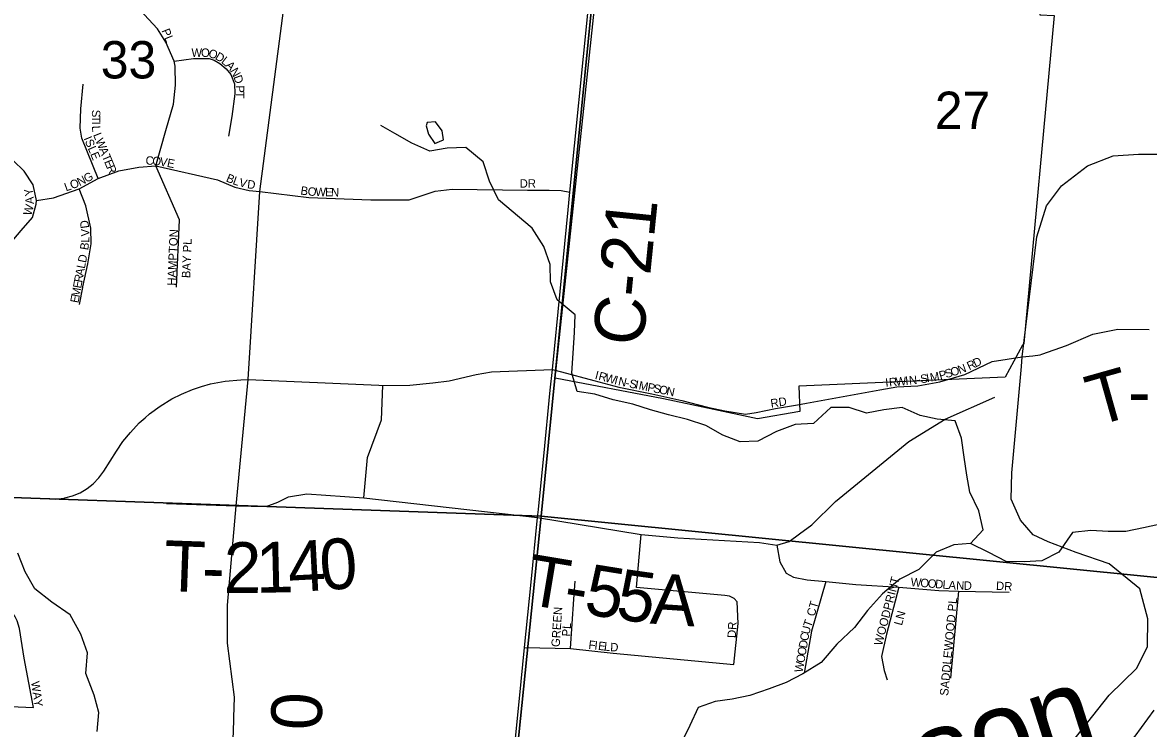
# Model space of a CAD drawing. Extents: x 1310247 to 1664935, y 284496 to 704931.
# Drawn here: x 1452162 to 1458833, y 480206 to 484384 of the extents above; entities that cross this region are included whole.
import ezdxf

# ---------------------------------------------------------------- set-up
doc = ezdxf.new("R2010")
doc.units = 0
for name, color, linetype in [('GM_P_State_Location', 7, 'Continuous'), ('GM_X_Corporation_Text', 7, 'Continuous'), ('GM_X_County', 7, 'Continuous'), ('GM_X_County_Road_Text', 7, 'Continuous'), ('GM_X_County_Subdivision_Text', 7, 'Continuous'), ('GM_X_Major_Lake_Text', 7, 'Continuous'), ('GM_X_Minor_Lake_Text', 7, 'Continuous'), ('GM_X_Minor_River', 7, 'Continuous'), ('GM_X_Minor_River_Text', 7, 'Continuous'), ('GM_X_Rail_Line', 7, 'Continuous'), ('GM_X_State_Location', 7, 'Continuous'), ('GM_X_State_Shield', 7, 'Continuous'), ('GM_X_Township_Road', 7, 'Continuous'), ('GM_X_Township_Subdivision', 7, 'Continuous'), ('GM_X_US_Location', 7, 'Continuous')]:
    doc.layers.add(name, color=color, linetype=linetype)

msp = doc.modelspace()

# ---------------------------------------------------------------- linework, layer by layer
at = {"layer": 'GM_X_Corporation_Text'}
for points in [[(1457240.8, 482210.7), (1457342.4, 482229.3), (1457466.3, 482234.8), (1457595.8, 482258.9), (1457743.8, 482301.5), (1457906.6, 482379.2), (1458084.2, 482405.1), (1458147.6, 482412.7)], [(1455354.4, 482317.2), (1455547.2, 482266.6), (1455694.9, 482227), (1455889.9, 482187.4), (1456069.2, 482147.9), (1456219.5, 482108.3), (1456322.3, 482087.2), (1456446.2, 482066.1), (1456509.5, 482076.7), (1456622.6, 482101.1), (1456753.5, 482121.5), (1456807.2, 482131.3)]]:
    msp.add_lwpolyline(points, dxfattribs=at)
at = {"layer": 'GM_X_County'}
for points in [[(1455772.4, 486880.5), (1455235.5, 481463.8), (1449969.8, 481647.7), (1450514.7, 486966.2)], [(1455772.4, 486880.5), (1461130.9, 486442.7), (1460590.1, 480930.2), (1455235.5, 481463.8)], [(1455235.5, 481463.8), (1454675.8, 475995.7), (1449464.2, 476312.3), (1449969.8, 481647.7)], [(1455235.5, 481463.8), (1460590.1, 480930.2), (1460069.6, 475529), (1454675.8, 475995.7)]]:
    msp.add_lwpolyline(points, close=True, dxfattribs=at)
at = {"layer": 'GM_X_County_Road_Text'}
for points in [[(1453375.8, 480739.7), (1453375.8, 480936.7), (1453428.9, 481523.2), (1453498.8, 482271.3), (1453567.4, 483383.7), (1453751.2, 484788.5), (1453817.5, 485658.8)], [(1455395.2, 483276.2), (1455405.6, 483381.2), (1455512.9, 484458.4)], [(1458271.1, 479989.5), (1458600.4, 480404), (1458763.2, 480563.1), (1458826.1, 480690.8), (1458829.7, 480855.5), (1458781.6, 481033.1), (1458600.4, 481181.1), (1458404.3, 481247.7), (1458237.8, 481310.7), (1458149, 481353.2), (1458075, 481438.3), (1458019.5, 481564.1), (1458023.2, 481719.5), (1458080.5, 482349), (1458084.2, 482405.1), (1458171.2, 483115.6), (1458228.5, 483298.8), (1458317.3, 483417.2), (1458470.6, 483537.3), (1458624.4, 483594.8), (1458772.6, 483604.9), (1459218.6, 483605.9)], [(1455347, 482792.6), (1455395.2, 483276.2)], [(1455282.7, 482147.8), (1455288.8, 482208.2), (1455301.1, 482331.2), (1455347, 482792.6)], [(1455255.9, 481879.1), (1455282.7, 482147.8)], [(1455218.3, 481502.9), (1455255.9, 481879.1)], [(1455175.3, 481073.1), (1455213.5, 481454.4), (1455218.3, 481502.9)], [(1454713.6, 476457.2), (1454761.4, 476935.6), (1454804.8, 477382.3), (1454822.6, 477547.1), (1454848.9, 477809.4), (1454853, 477851.8), (1454885.7, 478192.2), (1454911.9, 478438.9), (1454938.1, 478701.1), (1454941.6, 478737.5), (1454977.6, 479107.4), (1455006.3, 479383.1), (1455043, 479750.3), (1455049.2, 479812.4), (1455116.4, 480484.6), (1455136.6, 480686.4), (1455175.3, 481073.1)], [(1453414.5, 480270.9), (1453417.9, 480392.2), (1453375.8, 480710.5), (1453375.8, 480739.7)], [(1453375.4, 479748.5), (1453411.9, 480178), (1453414.5, 480270.9)]]:
    msp.add_lwpolyline(points, dxfattribs=at)
at = {"layer": 'GM_X_County_Subdivision_Text'}
for points in [[(1458201.8, 482421.7), (1458346.9, 482473.5), (1458502.3, 482540.1), (1458650.3, 482569.8), (1458837.4, 482567.3)], [(1458147.6, 482412.7), (1458191.5, 482418), (1458201.8, 482421.7)], [(1454274, 482238), (1454296.1, 482237.1), (1454456.7, 482238.1), (1454592.7, 482251.7), (1454690.5, 482264.3), (1454849.8, 482302.2), (1454941.3, 482317.9), (1455301.1, 482331.2)], [(1455301.1, 482331.2), (1455301.1, 482331.2), (1455354.4, 482317.2)], [(1452889.5, 482045.5), (1452915.5, 482068.5), (1452978.1, 482113.9), (1453047.9, 482156.9), (1453103.9, 482185.1), (1453169.4, 482212.9), (1453223.4, 482231), (1453276.5, 482245.8), (1453362.1, 482261.6), (1453455.8, 482269.8), (1453498.8, 482271.3)], [(1453498.8, 482271.3), (1454274, 482238)], [(1454185, 481571.9), (1454206.2, 481810), (1454289.8, 482032.4), (1454296.1, 482237.1)], [(1456807.2, 482131.3), (1457240.8, 482210.7)], [(1456766.2, 481357.7), (1456839.2, 481410.7), (1456978.4, 481549.9), (1457412.7, 481904.6), (1457627.3, 482037.8), (1457922.8, 482167.1)], [(1452412.6, 481570.8), (1452457.9, 481582.7), (1452504.8, 481601.8), (1452545.9, 481626.7), (1452581.8, 481654.9), (1452614.8, 481688.8), (1452643.9, 481729), (1452719.9, 481848.5), (1452756.8, 481904), (1452802.2, 481959), (1452854.3, 482014.4), (1452889.5, 482045.5)], [(1453428.9, 481523.2), (1453605.9, 481520.7), (1453675.2, 481545.5), (1453738.4, 481577.4), (1453846.5, 481594.2), (1454185, 481571.9), (1455213.5, 481454.4)], [(1451882.1, 481582.8), (1451891.6, 481582.4), (1452287.3, 481566.9), (1452355.1, 481564.3), (1452408.7, 481569.8), (1452412.6, 481570.8)], [(1453015, 481537), (1453428.9, 481523.2)], [(1455213.5, 481454.4), (1455827.9, 481354.4), (1456044, 481333.7), (1456528.3, 481307), (1456631.9, 481292.2), (1456704.4, 481312.9), (1456766.2, 481357.7)]]:
    msp.add_lwpolyline(points, dxfattribs=at)
at = {"layer": 'GM_X_Major_Lake_Text'}
msp.add_lwpolyline([(1458591.9, 489632.4), (1458545.1, 486934), (1458284.7, 486929.5), (1458188.3, 484430.7), (1458274.2, 484426.5), (1458093.9, 482484.6), (1458086.6, 482474.1), (1457984.5, 482286.4), (1456761.6, 482232.6), (1456766.4, 482083), (1456516.1, 482039), (1456258.5, 482093.4), (1455960.3, 482157.2), (1455317.1, 482279.9), (1455774.7, 486569.4), (1455792.3, 486820.8), (1455762.4, 486822.9), (1455732.4, 486822.4), (1455736.8, 486886.2), (1455716.9, 486888), (1455687.7, 486857.7), (1455526.7, 486817.6), (1452611.3, 486766.7), (1452779, 489168.6)], dxfattribs=at)
at = {"layer": 'GM_X_Minor_River'}
for points in [[(1454631.9, 483680.8), (1454655.4, 483691.2), (1454649.4, 483743.3), (1454609.3, 483797.4), (1454559.7, 483791.9)], [(1454559.7, 483791.9), (1454553.1, 483773.3), (1454567.2, 483723.2), (1454605.3, 483669.1), (1454631.9, 483680.8)]]:
    msp.add_lwpolyline(points, dxfattribs=at)
at = {"layer": 'GM_X_Minor_River_Text'}
for points in [[(1457779.1, 481300.7), (1457853.3, 481382.9), (1457827.2, 481495.2), (1457775, 481605.4), (1457757, 481705.7), (1457740.9, 481811.9), (1457724.8, 481924.2), (1457686.7, 482026.4), (1457580.3, 482036.4), (1457480, 482058.5), (1457373.7, 482106.6), (1457265.3, 482092.6), (1457163, 482072.5), (1457058.7, 482106.6), (1456950.3, 482106.6), (1456848, 482010.4), (1456739.7, 482006.4), (1456629.3, 481964.3), (1456519, 481906.1), (1456414.6, 481902.1), (1456310.3, 481942.2), (1456210, 482000.4), (1456101.6, 482034.4), (1455989.3, 482062.5), (1455882.9, 482092.6), (1455778.6, 482126.6), (1455662.2, 482150.7), (1455551.9, 482184.8), (1455447.5, 482200.8), (1455417.4, 482309.1), (1455425.4, 482427.4), (1455431.4, 482549.6), (1455435.4, 482653.9), (1455329.1, 482744.1), (1455290.9, 482850.3), (1455288.9, 482952.6), (1455250.8, 483058.8), (1455182.5, 483167.1), (1454981.9, 483335.5), (1454929.7, 483445.7), (1454891.5, 483560), (1454789.2, 483644.2), (1454678.8, 483640.2), (1454574.5, 483624.1), (1454468.2, 483670.3), (1454367.8, 483728.4), (1454285.6, 483774.5)], [(1458920.7, 481419), (1458802.4, 481392.9), (1458698, 481372.9), (1458593.7, 481372.9), (1458491.4, 481378.9), (1458383, 481366.8), (1458300.8, 481250.6), (1458200.5, 481198.5), (1458096.1, 481192.5), (1457989.8, 481194.5), (1457887.5, 481248.6), (1457779.1, 481300.7), (1457678.8, 481292.7), (1457574.4, 481250.6), (1457472.1, 481146.3), (1457359.8, 481090.2), (1457257.5, 481004), (1457167.2, 480903.8), (1457091, 480803.5), (1456986.7, 480705.3), (1456894.4, 480597), (1456786, 480528.9), (1456685.7, 480478.8), (1456585.4, 480440.7), (1456471.1, 480400.6), (1456366.7, 480380.5), (1456266.4, 480366.5), (1456164.1, 480330.4), (1456115.9, 480224.2), (1456045.6, 480081.8)], [(1452604.8, 480188.1), (1452614.8, 480300.3), (1452586.7, 480402.6), (1452536.5, 480530.9), (1452546.5, 480653.2), (1452508.4, 480765.4), (1452444.2, 480879.7), (1452335.8, 480953.9), (1452235.5, 481032.1), (1452177.3, 481134.3), (1452135.1, 481244.6)]]:
    msp.add_lwpolyline(points, dxfattribs=at)
at = {"layer": 'GM_X_State_Location'}
for points in [[(1452952.9, 483535.8), (1453011, 483745.3), (1453057, 483900.8), (1453069.1, 484014.3), (1453066.4, 484126.5), (1453061, 484156.2), (1453012.3, 484268.4), (1452962.3, 484348.1), (1452856.9, 484459), (1452767.7, 484514.4), (1452685.3, 484552.2), (1452556.9, 484572.5), (1452415, 484559)], [(1453061, 484156.2), (1453174.6, 484172.4), (1453228.6, 484172.4), (1453267.8, 484171.1), (1453297.6, 484161.6), (1453331.3, 484142.7), (1453369.2, 484110.3), (1453396.2, 484076.5), (1453417.8, 484022.4), (1453419.2, 483962.9), (1453403, 483827.8), (1453382.7, 483711.5)], [(1452609.6, 483461.5), (1452513.1, 483700.9), (1452503.1, 483758.8), (1452508.1, 483874.6), (1452521.3, 484020.2)], [(1452092.9, 482344.4), (1452018.5, 482397.3), (1451978.7, 482450.2), (1451953.9, 482506.5), (1451942.3, 482551.2), (1451937.4, 482648.8), (1451952.3, 482784.4), (1451995.3, 482915.1), (1452079.6, 483065.6), (1452154.1, 483153.3), (1452221.9, 483231.1), (1452243.4, 483308.8), (1452244.7, 483331.7), (1452225.2, 483423), (1452172.3, 483505.7), (1452107.8, 483568.5)], [(1452244.7, 483331.7), (1452346, 483346.6), (1452497.7, 483401.2), (1452609.6, 483461.5), (1452732.6, 483506.1), (1452851.9, 483528.7), (1452952.9, 483535.8), (1453316.8, 483452.7), (1453420.6, 483410.9), (1453504.2, 483390.7), (1453567.4, 483383.7)], [(1453074.7, 482817.4), (1453093, 483215.9), (1452952.9, 483535.8)], [(1452500.1, 482715.4), (1452520.4, 482815.4), (1452520.4, 482819.5), (1452548.8, 482956), (1452569, 483075), (1452567.7, 483166.8), (1452538, 483299.3), (1452497.7, 483401.2)], [(1453567.4, 483383.7), (1453858.4, 483349.2), (1454226.8, 483335.5), (1454452, 483335.5), (1454606, 483386.3), (1454706.9, 483398.2), (1455153.6, 483391.8), (1455281.4, 483392.8), (1455352.5, 483390.8), (1455405.6, 483381.2)], [(1451678, 480354), (1452227.4, 480330.3), (1452172.4, 480622.9), (1452160.9, 480697.9), (1452144.5, 480797.8), (1452131.4, 480843.5), (1452116.8, 480870.9), (1452096.1, 480899.6), (1452077.7, 480921.6), (1452058.1, 480945.7), (1452042.7, 480974.3), (1452018.8, 481018.9), (1451978.4, 481105.4), (1451935.1, 481208.6), (1451880.5, 481340.4), (1451891.6, 481582.4)], [(1455136.6, 480686.4), (1455408.8, 480679.2), (1455660.5, 480652.5), (1456377, 480584.1), (1456402.7, 480828), (1456396.2, 480956.4), (1456377.6, 480975), (1456363.1, 480984.2), (1456349.9, 480989.5), (1456322.4, 480993.3), (1455800.5, 481040.8), (1455827.9, 481354.4)], [(1456631.9, 481292.2), (1456648.2, 481193), (1456686.7, 481126.4), (1456729, 481101.9), (1456811.1, 481086.4), (1456920.6, 481076), (1457099.8, 481058.3), (1457353, 481043.5), (1457591.4, 481022.7), (1457706.9, 481018.3), (1458007.5, 481013.8)], [(1455408.8, 480679.2), (1455428.1, 480972.4), (1455435.4, 481077.5)], [(1456920.6, 481076), (1456836.2, 480782.8), (1456793.3, 480534.1)], [(1457353, 481043.5), (1457280.5, 480765.1), (1457250.8, 480633.3), (1457267.1, 480548.9), (1457284.9, 480494.1)], [(1457706.9, 481018.3), (1457659.5, 480504.5)]]:
    msp.add_lwpolyline(points, dxfattribs=at)
at = {"layer": 'GM_X_State_Shield'}
msp.add_lwpolyline([(1456800.8, 478265.5), (1456819.9, 478282.7), (1457013.8, 478449.2), (1457150.7, 478574.8), (1457308.1, 478724), (1457514.5, 478912.4), (1457729, 479106.6), (1457937.4, 479298.9), (1458092.8, 479442.1), (1458233.9, 479575.6), (1458381.4, 479729.1), (1458496.4, 479863.1), (1458625.8, 480013), (1458753.1, 480160.8), (1458866.5, 480315)], dxfattribs=at)

# ---------------------------------------------------------------- texts
at = {"layer": 'GM_P_State_Location'}
for s, rotation, p in [('PL', 291.69565, (1452985.2, 484336.9)), ('W', 359.51246, (1453162.6, 484181.6)), ('O', 359.51909, (1453219.8, 484181.1)), ('O', 343.78439, (1453260.2, 484181.3)), ('D', 329.00251, (1453299.3, 484170.4)), ('L', 321.73692, (1453335.6, 484148.6)), ('A', 313.34577, (1453361.9, 484128.1)), ('N', 299.72321, (1453390.2, 484098.7)), ('D', 289.91403, (1453411.1, 484062.5)), ('P', 271.55776, (1453426.1, 484012.1)), ('T', 268.03258, (1453427.1, 483977.7)), ('S', 269.86338, (1452573.7, 483868.2)), ('T', 269.88232, (1452573.6, 483833)), ('I', 269.86888, (1452573.5, 483797.8)), ('L', 273.55504, (1452573.6, 483772.3)), ('L', 291.81095, (1452579.6, 483720.3)), ('ISLE', 292.9343, (1452523.5, 483698.7)), ('W', 292.54217, (1452592.9, 483687)), ('A', 292.55182, (1452614.8, 483634.1)), ('T', 292.55528, (1452631.7, 483593.5)), ('E', 292.55528, (1452645.2, 483561)), ('R', 292.56107, (1452658.7, 483528.4)), ('C', 358.11501, (1452890.7, 483543.6)), ('O', 354.34503, (1452929.4, 483542.4)), ('V', 350.57506, (1452972.4, 483538.2)), ('E', 348.69007, (1453015.3, 483531)), ('N', 26.78168, (1452500.9, 483414.9)), ('G', 27.64337, (1452540.9, 483435.1)), ('B', 337.02145, (1453364.4, 483446)), ('L', 340.57365, (1453404, 483429.4)), ('V', 345.56897, (1453441.7, 483416.3)), ('Y', 101.45654, (1452227.9, 483363.2)), ('L', 19.6189, (1452420.4, 483384.7)), ('O', 20.97915, (1452454.7, 483397)), ('D', 353.04598, (1453491.2, 483404)), ('B', 351.19659, (1453806.8, 483367.5)), ('O', 356.24318, (1453850.6, 483360.9)), ('W', 358.58763, (1453896.8, 483357.9)), ('E', 358.59946, (1453954, 483356.5)), ('N', 358.59662, (1453989.2, 483355.6)), ('DR', 0.00001, (1455107.5, 483407.2)), ('A', 92.13508, (1452230.6, 483310.4)), ('W', 74.58118, (1452213.4, 483238.7)), ('D', 98.59042, (1452557.6, 483169.9)), ('V', 91.16462, (1452559.1, 483119)), ('HAMPTON', 87.51181, (1453069.7, 482826.2)), ('B', 80.63348, (1452550.8, 483034.9)), ('L', 88.04732, (1452557.9, 483080.9)), ('BAY PL', 87.66396, (1453155.6, 482871.1)), ('D', 77.44274, (1452537.7, 482959.3)), ('L', 79.03295, (1452531.1, 482925.1)), ('R', 79.49967, (1452515.9, 482843.1)), ('A', 79.4918, (1452523.1, 482882)), ('M', 79.48663, (1452499.8, 482756.5)), ('E', 79.51094, (1452509.5, 482808.4)), ('E', 79.50453, (1452493.4, 482721.9)), ('WOODPRINT', 75.46732, (1457254.2, 480693.7)), ('W', 355.62451, (1457422.6, 481048.8)), ('O', 355.61232, (1457479.6, 481044.4)), ('O', 355.62476, (1457523.5, 481041.1)), ('D', 355.61232, (1457567.3, 481037.7)), ('L', 355.62435, (1457611.2, 481034.3)), ('A', 355.61232, (1457646.3, 481031.7)), ('N', 358.32641, (1457692.8, 481028.2)), ('D', 359.92533, (1457738.3, 481026.9)), ('DR', 356.81008, (1457928.4, 481026.8)), ('CT', 73.60558, (1456854, 480866.1)), ('SADDLEWOOD PL', 84.67348, (1457645.7, 480397.9)), ('GREEN', 86.27045, (1455344.5, 480687.2)), ('LN', 74.48215, (1457371.6, 480812.4)), ('PL', 86.42535, (1455407.4, 480749.5)), ('DR', 86.98841, (1456387.9, 480740.7)), ('U', 76.34016, (1456822.9, 480759.6)), ('T', 70.8221, (1456833, 480801.1)), ('F', 353.48485, (1455513.3, 480678.5)), ('D', 80.01241, (1456808.6, 480678.1)), ('C', 79.99061, (1456816.2, 480721.4)), ('I', 353.47151, (1455548.3, 480674.5)), ('E', 353.49922, (1455570.2, 480672)), ('L', 353.48485, (1455605.2, 480668)), ('D', 356.41869, (1455642.9, 480663.8)), ('O', 79.98441, (1456800.9, 480634.7)), ('W', 79.99591, (1456783.4, 480535)), ('O', 80.01241, (1456793.3, 480591.4)), ('WAY', 278.36756, (1452212.8, 480482))]:
    msp.add_text(s, height=50, rotation=rotation, dxfattribs=at).set_placement(p)
at = {"layer": 'GM_X_Minor_Lake_Text'}
msp.add_text('Simpson', height=499.97, rotation=17.7127, dxfattribs=at).set_placement((1456080.3, 479324.1))
at = {"layer": 'GM_X_Rail_Line'}
for s, rotation, p in [('D', 24.91334, (1457806.9, 482342.2)), ('S', 16.91563, (1457634.6, 482279.2)), ('O', 16.97447, (1457668.4, 482289.4)), ('N', 19.92359, (1457713.1, 482303.2)), ('R', 24.81585, (1457770.9, 482325.6)), ('I', 345.18968, (1455549.9, 482276.1)), ('R', 345.19513, (1455571.1, 482270.5)), ('W', 345.20517, (1455609.4, 482260.4)), ('I', 345.44574, (1455665, 482245.7)), ('N', 347.43223, (1455688.1, 482239.7)), ('S', 348.55149, (1455753.7, 482225.5)), ('I', 348.56151, (1455788.2, 482218.5)), ('M', 348.54004, (1455809.7, 482214.2)), ('I', 5.34086, (1457275.8, 482228)), ('R', 5.35176, (1457297.7, 482230)), ('W', 5.35405, (1457337.1, 482233.7)), ('I', 5.37804, (1457394.1, 482239)), ('N', 5.78868, (1457416.4, 482241.2)), ('-', 7.97369, (1457462.2, 482245.8)), ('S', 9.367, (1457485.3, 482249.1)), ('I', 9.60277, (1457520.3, 482254.9)), ('M', 10.41089, (1457542.8, 482258.6)), ('P', 15.75217, (1457599.6, 482269.3)), ('-', 348.43672, (1455732, 482230)), ('P', 348.52931, (1455861.5, 482203.7)), ('S', 348.52744, (1455896, 482196.7)), ('O', 348.54095, (1455930.4, 482189.7)), ('N', 348.53575, (1455973.6, 482181)), ('RD', 8.96908, (1456597.6, 482104.7))]:
    msp.add_text(s, height=50, rotation=rotation, dxfattribs=at).set_placement(p)
at = {"layer": 'GM_X_Township_Road'}
for s, rotation, p in [('C-21', 84.18706, (1455837.5, 482463.5)), ('0', 88.14703, (1453932.8, 480192.3))]:
    msp.add_text(s, height=300, rotation=rotation, dxfattribs=at).set_placement(p)
at = {"layer": 'GM_X_Township_Subdivision'}
for s, rotation, p in [('T', 15.74525, (1458517.4, 481993.7)), ('-', 0.02342, (1458711.9, 482051.6)), ('0', 4.16894, (1453932.9, 481023.1)), ('T', 357.94679, (1452995.9, 481020.8)), ('2', 359.721, (1453353.4, 481009.2)), ('1', 1.32207, (1453547.4, 481008.4)), ('4', 3.00571, (1453741.7, 481013)), ('T', 350.54613, (1455136.2, 480943.3)), ('-', 358.47285, (1453223.1, 481012.6)), ('5', 350.85213, (1455480.8, 480886)), ('5', 352.00442, (1455669.8, 480855.6)), ('A', 356.20741, (1455876.7, 480827.5)), ('-', 350.59602, (1455357.8, 480906.4))]:
    msp.add_text(s, height=300, rotation=rotation, dxfattribs=at).set_placement(p)
at = {"layer": 'GM_X_US_Location'}
for s, p in [('33', (1452625.9, 484053.7)), ('27', (1457567.1, 483754.5))]:
    msp.add_text(s, height=221, rotation=0.00001, dxfattribs=at).set_placement(p)

doc.saveas('drawing.dxf')
